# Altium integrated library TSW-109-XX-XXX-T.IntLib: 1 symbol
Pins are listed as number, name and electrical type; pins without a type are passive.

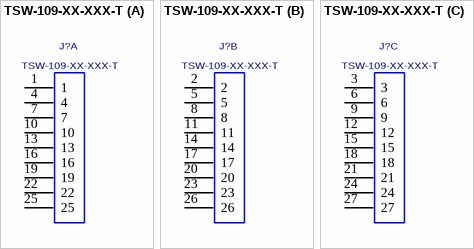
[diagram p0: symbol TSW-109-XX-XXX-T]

## TSW-109-XX-XXX-T
designator J?
.025[0.64] SQ. POST TERMINAL STRIP ASSEMBLY.; MANUFACTURER: SAMTEC
footprint TSW-109-XX-XXX-T
part A pins: 1, 4, 7, 10, 13, 16, 19, 22, 25
part B pins: 2, 5, 8, 11, 14, 17, 20, 23, 26
part C pins: 3, 6, 9, 12, 15, 18, 21, 24, 27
